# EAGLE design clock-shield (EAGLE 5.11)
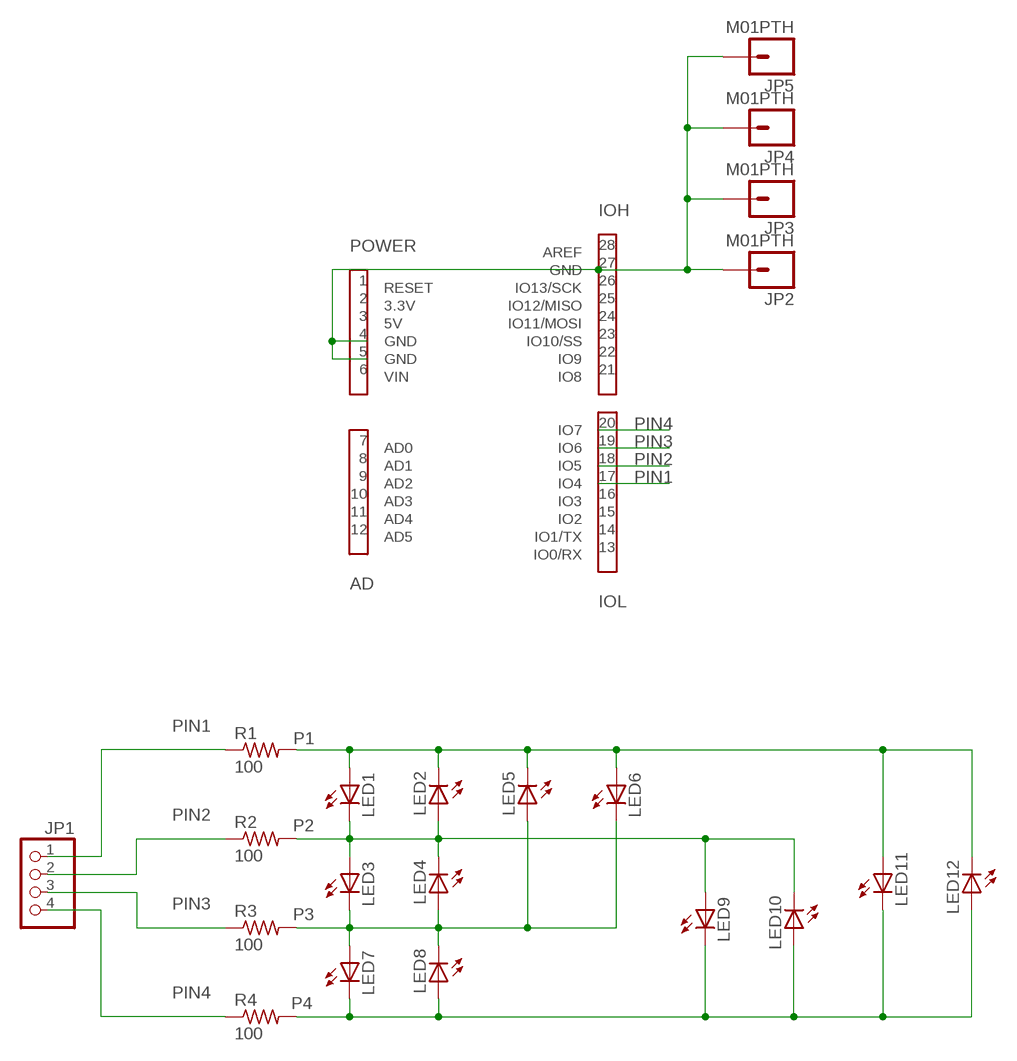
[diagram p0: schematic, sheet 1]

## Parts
JP1  PINHD-1X4  [1X04]
JP2  M01PTH  [1X01]
JP3  M01PTH  [1X01]
JP4  M01PTH  [1X01]
JP5  M01PTH  [1X01]
LED1  LEDCHIPLED_0805  [CHIPLED_0805]
LED2  LEDCHIPLED_0805  [CHIPLED_0805]
LED3  LEDCHIPLED_0805  [CHIPLED_0805]
LED4  LEDCHIPLED_0805  [CHIPLED_0805]
LED5  LEDCHIPLED_0805  [CHIPLED_0805]
LED6  LEDCHIPLED_0805  [CHIPLED_0805]
LED7  LEDCHIPLED_0805  [CHIPLED_0805]
LED8  LEDCHIPLED_0805  [CHIPLED_0805]
LED9  LEDCHIPLED_0805  [CHIPLED_0805]
LED10  LEDCHIPLED_0805  [CHIPLED_0805]
LED11  LEDCHIPLED_0805  [CHIPLED_0805]
LED12  LEDCHIPLED_0805  [CHIPLED_0805]
R1  100  R-US_R0805  [R0805]
R2  100  R-US_R0805  [R0805]
R3  100  R-US_R0805  [R0805]
R4  100  R-US_R0805  [R0805]
U$1  ARDUINO-SHIELD-HEADERS  [ARDUINO-SHIELD-HEADERS]

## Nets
GND: JP2.1 JP3.1 JP4.1 JP5.1 U$1.4(GND) U$1.5(GND) U$1.27(GND)
P1: LED1.A LED2.C LED5.C LED6.A LED11.A LED12.C R1.2
P2: LED1.C LED2.A LED3.A LED4.C LED9.A LED10.C R2.2
P3: LED3.C LED4.A LED5.A LED6.C LED7.A LED8.C R3.2
P4: LED7.C LED8.A LED9.C LED10.A LED11.C LED12.A R4.2
PIN1: JP1.1 R1.1 U$1.17(IO4)
PIN2: JP1.2 R2.1 U$1.18(IO5)
PIN3: JP1.3 R3.1 U$1.19(IO6)
PIN4: JP1.4 R4.1 U$1.20(IO7)
Unconnected: U$1.1(RESET) U$1.2(3.3V) U$1.3(5V) U$1.6(VIN) U$1.7(AD0) U$1.8(AD1) U$1.9(AD2) U$1.10(AD3) U$1.11(AD4) U$1.12(AD5) U$1.13(IO0/RX) U$1.14(IO1/TX) U$1.15(IO2) U$1.16(IO3) U$1.21(IO8) U$1.22(IO9) U$1.23(IO10/SS) U$1.24(IO11/MOSI) U$1.25(IO12/MISO) U$1.26(IO13/SCK) U$1.28(AREF)

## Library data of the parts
JP1 = pinhead:PINHD-1X4: PIN HEADER
JP2-JP5 = SparkFun:M01: Header 1
LED1-LED12 = led:LED: LED
R1-R4 = resistor:R-US_: RESISTOR, American symbol
U$1 = trl:ARDUINO-SHIELD-HEADERS

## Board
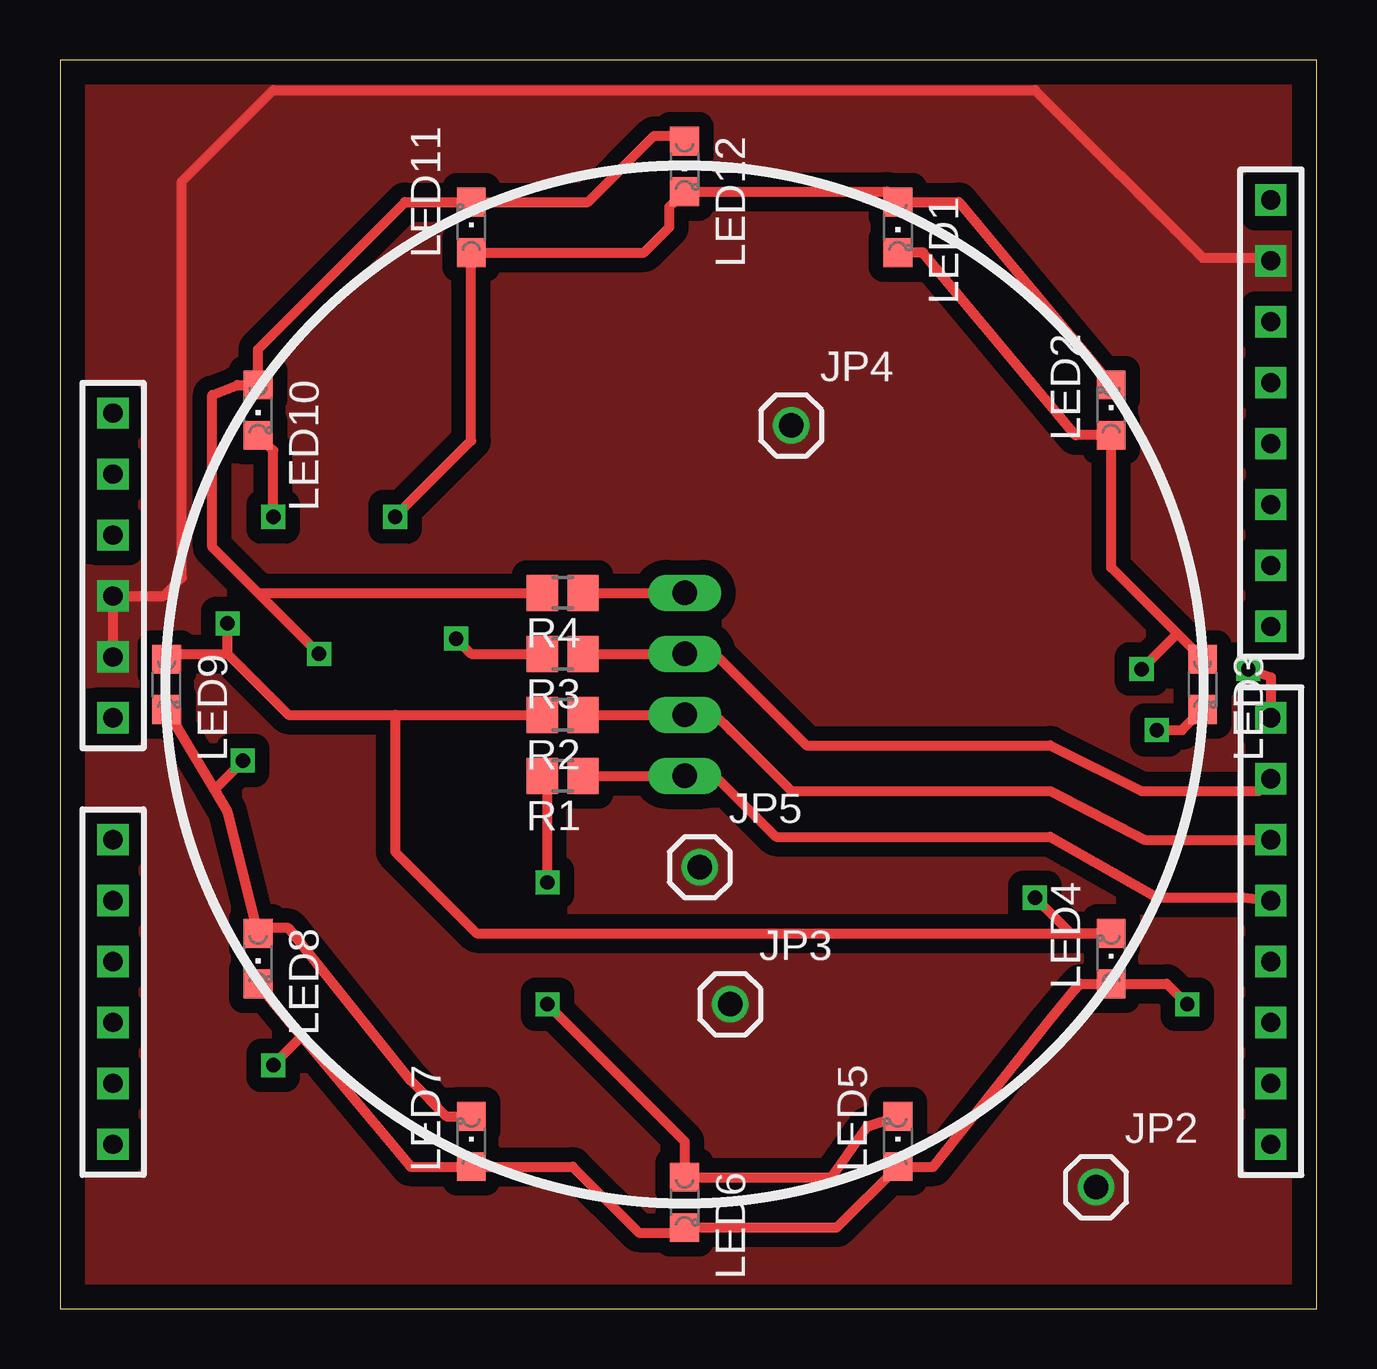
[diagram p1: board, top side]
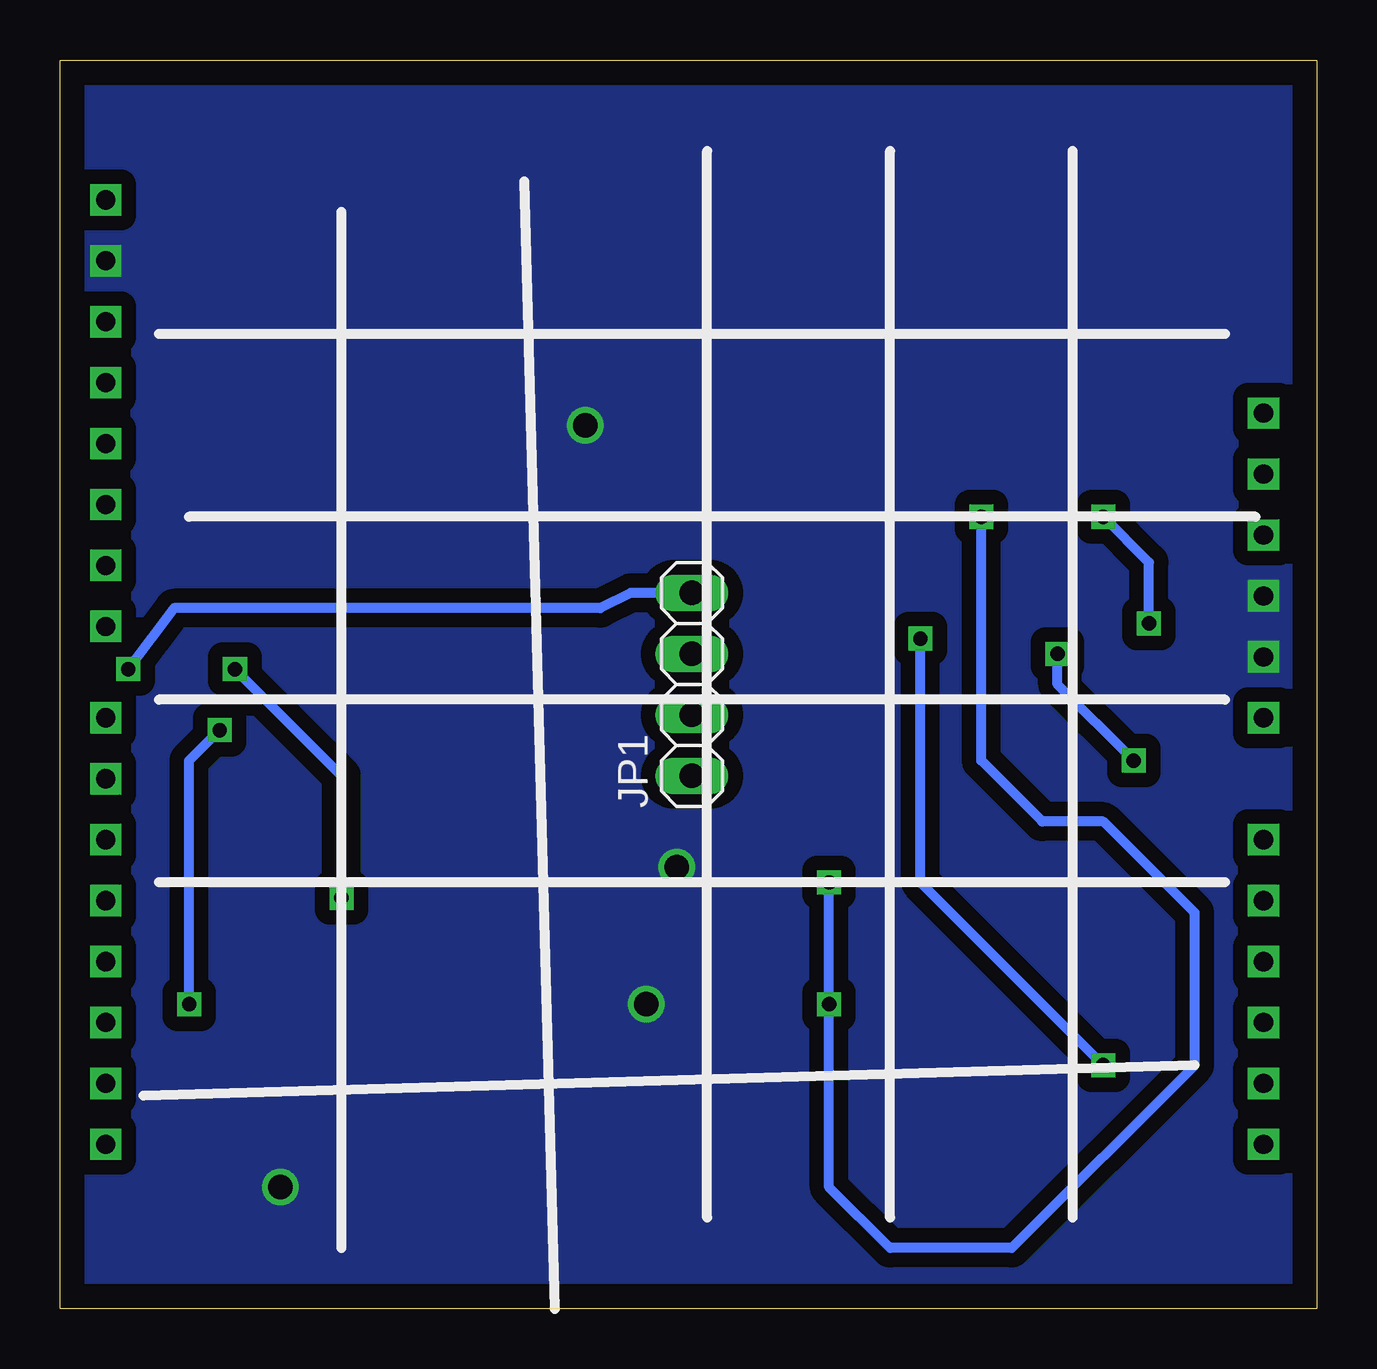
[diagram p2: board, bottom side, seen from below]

Size 52.38 x 52.06 mm. Coordinates in mm from the lower left corner, seen from the top.
Outline: 0,0 52.38,0 52.38,52.06 0,52.06 0,0
Copper layers (1*16): Top 0.035mm / dielectric 1.5mm / Bottom 0.035mm
Design rules "default": minimum track width 10mil, minimum drill 0.6mm, track to track 8mil, track to pad 8mil, pad to pad 8mil, via to via 8mil, smd to smd 8mil, copper to edge 40mil, drill to drill 8mil, minimum pad ring 10mil, minimum via ring 8mil, stop-mask expansion 4mil, vias tented up to drill 0mil, thermal gap 10mil

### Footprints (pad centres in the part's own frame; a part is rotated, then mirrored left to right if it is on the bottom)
1X04 = drill 1.016 long: 1 -3.81,0; 2 -1.27,0; 3 1.27,0; 4 3.81,0
1X01 = drill 1.016 round: 1 0,0
CHIPLED_0805 = smd 1.2 x 1.2: A 0,-1.05; C 0,1.05
R0805 = smd 1.3 x 1.5: 1 -0.85,0; 2 0.85,0
ARDUINO-SHIELD-HEADERS = drill 0.8 square: 1 -24.46,13.21; 2 -24.46,10.67; 3 -24.46,8.13; 4 -24.46,5.59; 5 -24.46,3.05; 6 -24.46,0.51; 7 -24.46,-4.57; 8 -24.46,-7.11; 9 -24.46,-9.65; 10 -24.46,-12.19; 11 -24.46,-14.73; 12 -24.46,-17.27; 13 23.8,-17.27; 14 23.8,-14.73; 15 23.8,-12.19; 16 23.8,-9.65; 17 23.8,-7.11; 18 23.8,-4.57; 19 23.8,-2.03; 20 23.8,0.51; 21 23.8,4.32; 22 23.8,6.86; 23 23.8,9.4; 24 23.8,11.94; 25 23.8,14.48; 26 23.8,17.02; 27 23.8,19.56; 28 23.8,22.1

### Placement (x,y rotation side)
JP1  26.04,26.04 90 bottom
JP2  43.18,5.08 0 top
JP3  27.94,12.7 0 top
JP4  30.48,36.83 0 top
JP5  26.67,18.41 0 top
LED1  34.92,45.09 180 top
LED2  43.81,37.47 0 top
LED3  47.62,26.04 180 top
LED4  43.81,14.61 0 top
LED5  34.92,6.99 0 top
LED6  26.04,4.45 180 top
LED7  17.14,6.99 0 top
LED8  8.26,14.61 180 top
LED9  4.45,26.04 180 top
LED10  8.26,37.47 180 top
LED11  17.14,45.09 0 top
LED12  26.04,47.62 180 top
R1  20.95,22.23 180 top
R2  20.95,24.77 180 top
R3  20.95,27.3 180 top
R4  20.95,29.84 180 top
U$1  26.67,24.13 0 top

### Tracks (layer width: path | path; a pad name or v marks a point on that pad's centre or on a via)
GND
  Top 0.406: U$1.5 U$1.4 4.32,29.72 5.08,30.48 5.08,46.99 8.89,50.8 40.64,50.8 47.62,43.81 50.34,43.81 U$1.27
  pour Top (isolate 0.61, no thermals): 0,52.07 52.07,52.07 52.07,0 0,0
  pour Bottom (isolate 0.61, no thermals): 0,52.07 52.07,52.07 52.07,0 0,0 0,1.27
P1  (via drill 0.6)
  Top 0.406: LED2.C 37.47,46.13 LED1.A 34.48,46.58 LED12.C 25.4,45.94 25.4,45.09 24.35,44.03 LED11.A 17.14,36.2 v13.97,33.02 | LED5.C 33.66,7.62 32.16,5.5 LED6.A 26.04,6.99 v20.32,12.7 | v20.32,17.78 20.32,22.01 R1.2
  Bottom 0.406: v20.32,17.78 v20.32,12.7 20.32,5.08 17.78,2.54 12.7,2.54 5.08,10.16 5.08,16.51 8.89,20.32 11.43,20.32 13.97,22.86 v13.97,33.02
P2  (via drill 0.6)
  Top 0.406: LED1.C 35.98,44.03 42.33,36.41 LED2.A 43.81,30.89 46.56,28.15 | 13.97,24.77 9.53,24.77 6.99,27.3 | 13.97,24.77 R2.2 | 6.99,27.3 4.67,27.3 LED9.A | 46.56,28.15 LED3.A | 13.97,24.77 13.97,19.05 17.36,15.65 LED4.C 42.13,15.65 v40.64,17.14 | 6.99,27.3 v6.99,28.57 | v8.89,33.02 8.89,35.78 LED10.C | v45.09,26.67 46.56,28.15
  Bottom 0.406: v6.99,28.57 6.99,31.11 v8.89,33.02 | v40.64,17.14 40.64,22.23 v45.09,26.67
P3  (via drill 0.6)
  Top 0.406: 47.84,24.98 LED3.C 46.77,24.13 v45.72,24.13 | 10.08,11.36 14.61,5.93 LED7.A 21.37,5.93 24.13,3.17 25.82,3.17 LED6.C 32.38,3.4 LED5.A 36.41,5.93 41.27,12.06 42.33,13.34 42.55,13.55 LED4.A 46.13,13.55 v46.99,12.7 | 10.08,11.36 LED8.C | R3.2 17.14,27.3 v16.51,27.94 | v8.89,10.16 8.89,10.17 10.08,11.36
  Bottom 0.406: v16.51,27.94 16.51,17.78 v8.89,10.16 | v46.99,12.7 46.99,22.86 v45.72,24.13
P4  (via drill 0.6)
  Top 0.406: LED12.A 25.82,48.9 24.77,48.9 22,46.13 LED11.C 14.38,46.13 8.26,40.01 LED10.A 7.4,38.52 6.35,38.1 6.35,31.75 8.26,29.84 | 6.44,21.64 6.99,20.73 LED8.A 8.47,15.88 9.53,15.88 14.61,9.53 16.09,8.04 LED7.C | 6.44,21.64 LED9.C 4.22,24.77 | 8.26,29.84 R4.2 | v10.79,27.3 8.26,29.84 | v7.62,22.86 7.62,22.82 6.44,21.64
  Bottom 0.406: v10.79,27.3 10.79,26.04 v7.62,22.86
PIN1
  Top 0.406: R1.1 JP1.1 27.3,22.23 29.84,19.68 41.27,19.68 45.72,17.14 49.33,17.14 U$1.17
PIN2
  Top 0.406: R2.1 JP1.2 27.3,24.77 27.94,24.13 30.48,21.59 41.27,21.59 45.21,19.56 U$1.18
PIN3
  Top 0.406: R3.1 JP1.3 27.3,27.3 31.11,23.5 41.27,23.5 45.09,21.59 49.96,21.59 U$1.19
PIN4  (via drill 0.6)
  Top 0.406: R4.1 JP1.4 | U$1.20 50.47,26.34 v49.53,26.67
  Bottom 0.406: v49.53,26.67 47.62,29.21 29.84,29.21 28.57,29.84 JP1.4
